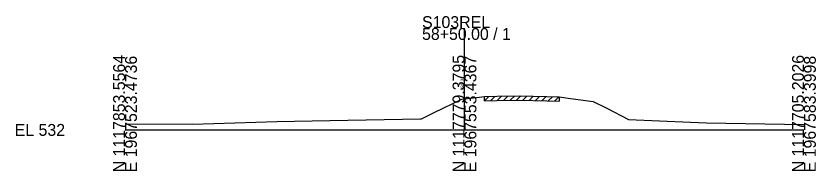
# Model space of a CAD drawing. Extents: x -26 to 163, y -10 to 24518.
# Drawn here: x -25.7 to 162.8, y 8990.3 to 9026.9 of the extents above; entities that cross this region are included whole.
import ezdxf

# ---------------------------------------------------------------- set-up
doc = ezdxf.new("R2010")
doc.units = 0
for name, color, linetype in [('RD_GPK_XS_Cell', 7, 'Continuous'), ('RD_XS_ExGround', 7, 'Continuous'), ('RD_XS_ExPaveRet', 7, 'Continuous'), ('RD_XS_TX_Elev_EX', 7, 'Continuous')]:
    doc.layers.add(name, color=color, linetype=linetype)

msp = doc.modelspace()

# ---------------------------------------------------------------- linework, layer by layer
at = {"layer": 'RD_GPK_XS_Cell'}
for p, q in [((80, 9000), (80, 9024.03)), ((0, 9000), (80, 9000)), ((80, 9000), (160, 9000))]:
    msp.add_line(p, q, dxfattribs=at)
at = {"layer": 'RD_XS_ExGround'}
msp.add_lwpolyline([(0, 9001.47), (15.98, 9001.37), (35.74, 9001.97), (48.26, 9002.2), (69.63, 9002.59), (69.89, 9002.63), (72.87, 9004.09), (79.35, 9007.23), (80, 9007.31), (82.84, 9007.66), (84.73, 9007.89), (87.71, 9007.93), (93.07, 9008.01), (99.37, 9007.85), (102.34, 9007.77), (104.98, 9007.43), (110.29, 9006.72), (113.54, 9005.12), (118.62, 9002.42), (133.25, 9001.85), (137.05, 9001.7), (160, 9001.3)], dxfattribs=at)
at = {"layer": 'RD_XS_ExPaveRet'}
for p, q in [((84.73, 9006.89), (85.75, 9007.91)), ((84.73, 9006.89), (84.73, 9007.89)), ((84.73, 9006.89), (87.71, 9006.93)), ((86.23, 9006.91), (87.25, 9007.93)), ((87.71, 9006.93), (93.07, 9007.01)), ((87.73, 9006.93), (88.75, 9007.95)), ((89.23, 9006.95), (90.25, 9007.97)), ((90.73, 9006.98), (91.75, 9007.99)), ((92.23, 9007), (93.24, 9008.01)), ((93.07, 9007.01), (99.37, 9006.85)), ((93.73, 9006.99), (94.71, 9007.97)), ((95.23, 9006.96), (96.21, 9007.93)), ((96.73, 9006.92), (97.71, 9007.89)), ((98.23, 9006.88), (99.21, 9007.86)), ((99.37, 9006.85), (102.34, 9006.77)), ((99.73, 9006.84), (100.71, 9007.82)), ((101.23, 9006.8), (102.21, 9007.78)), ((102.34, 9007.77), (102.34, 9006.77))]:
    msp.add_line(p, q, dxfattribs=at)

# ---------------------------------------------------------------- texts
at = {"layer": 'RD_GPK_XS_Cell'}
for s, p in [('S103REL', (70, 9024.03)), ('58+50.00 / 1', (70, 9021.23)), ('EL 532', (-26, 8998.6))]:
    msp.add_text(s, height=2.8, dxfattribs=at).set_placement(p)
for s, p in [('N 1117853.5564', (0, 8990)), ('N 1117779.3795', (80, 8990)), ('N 1117705.2026', (160, 8990)), ('E 1967523.4736', (2.8, 8990)), ('E 1967553.4367', (82.8, 8990)), ('E 1967583.3998', (162.8, 8990))]:
    msp.add_text(s, height=2.8, rotation=90, dxfattribs=at).set_placement(p)
at = {"layer": 'RD_XS_TX_Elev_EX'}
msp.add_text('539.31', height=0.8, rotation=90, dxfattribs=at).set_placement((79.9, 9009.31))

doc.saveas('drawing.dxf')
